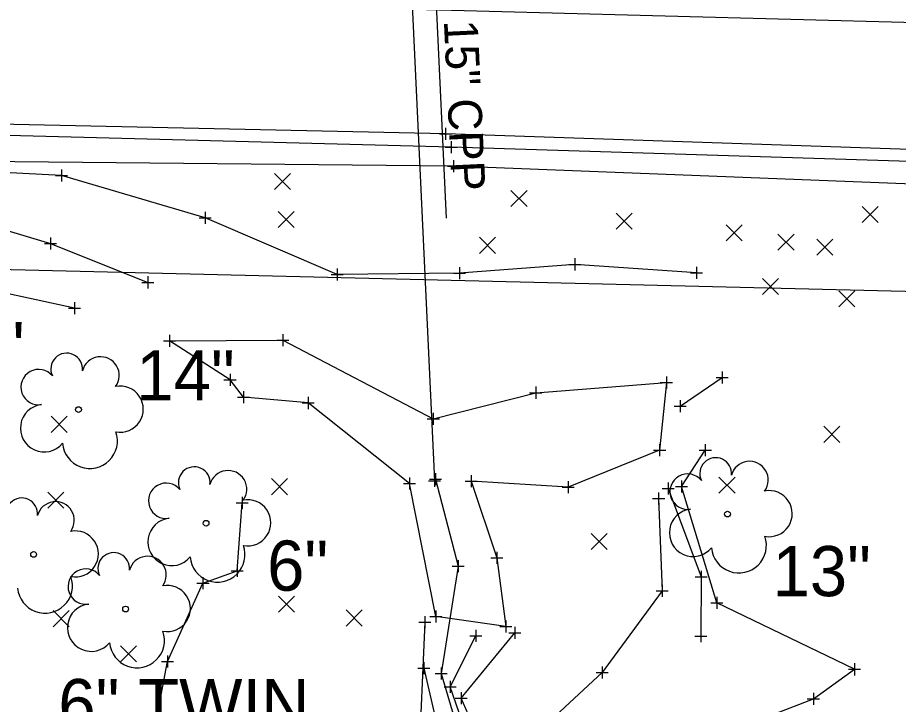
# Model space of a CAD drawing. Extents: x 2005176 to 2005823, y 572472 to 572942.
# Drawn here: x 2005491.4 to 2005564.6, y 572551.1 to 572608.1 of the extents above; entities that cross this region are included whole.
import ezdxf

# ---------------------------------------------------------------- set-up
doc = ezdxf.new("R2010")
doc.units = 0
for name, color, linetype in [('_CIVIL_CONSTRUCTION', 7, 'Continuous'), ('DR_X_Storm_Sewer', 7, 'Continuous'), ('DR_X_Text', 7, 'Continuous'), ('GE_X_Alignment_100_Bearings', 7, 'Continuous'), ('GE_X_Alignment_100_Cardinal_Points', 7, 'Continuous'), ('GE_X_Alignment_100_Distances', 7, 'Continuous'), ('GE_X_Alignment_100_Stations', 7, 'Continuous'), ('GE_X_Alignment_500_Bearings', 7, 'Continuous'), ('GE_X_Alignment_500_Cardinal_Points', 7, 'Continuous'), ('GE_X_Alignment_500_Curve_Data', 7, 'Continuous'), ('GE_X_Alignment_500_Distances', 7, 'Continuous'), ('SC_Scratch10', 7, 'Continuous'), ('SC_Scratch8', 7, 'Continuous'), ('SV_P_Mon_Cells_Set', 7, 'Continuous'), ('SV_X_Random_Point', 7, 'Continuous'), ('SV_X_Shot_Marker', 7, 'Continuous'), ('UT_X_Overhead_Telecom', 7, 'Continuous'), ('VG_X_Text', 7, 'Continuous')]:
    doc.layers.add(name, color=color, linetype=linetype)

msp = doc.modelspace()

# ---------------------------------------------------------------- linework, layer by layer
at = {"layer": '_CIVIL_CONSTRUCTION'}
for p, q in [((2005525.539, 572569.63), (2005526.539, 572569.63)), ((2005526.039, 572570.13), (2005526.039, 572569.13)), ((2005526.039, 572569.63), (2005526.039, 572569.63))]:
    msp.add_line(p, q, dxfattribs=at)
at = {"layer": 'DR_X_Storm_Sewer'}
msp.add_line((2005522.925, 572635.917), (2005526.039, 572569.63), dxfattribs=at)
at = {"layer": 'DR_X_Text'}
msp.add_line((2005527.042, 572591.446), (2005526.156, 572610.296), dxfattribs=at)
at = {"layer": 'GE_X_Alignment_100_Bearings'}
msp.add_lwpolyline([(2005818.636, 572588.972), (2005775.196, 572590.402), (2005728.29, 572591.88), (2005676.677, 572593.613), (2005626.55, 572595.194), (2005577.828, 572596.717), (2005526.97, 572598.442), (2005477.007, 572599.528), (2005423.668, 572600.697), (2005368.746, 572601.993), (2005321.745, 572602.994), (2005266.716, 572604.351), (2005220.033, 572605.659)], dxfattribs=at)
at = {"layer": 'GE_X_Alignment_100_Cardinal_Points'}
msp.add_lwpolyline([(2005220.502, 572615.986), (2005272.509, 572614.367), (2005322.2, 572613.202), (2005370.615, 572612.292), (2005424.944, 572611.274), (2005476.504, 572610.167), (2005524.324, 572608.789), (2005576.491, 572607.397), (2005627.688, 572605.768), (2005677.107, 572603.684), (2005728.026, 572601.917), (2005776.184, 572600.497), (2005820.14, 572599.28)], dxfattribs=at)
at = {"layer": 'GE_X_Alignment_100_Distances'}
msp.add_lwpolyline([(2005818.697, 572589.047), (2005775.196, 572590.402), (2005728.29, 572591.88), (2005676.677, 572593.613), (2005626.55, 572595.194), (2005577.828, 572596.717), (2005526.97, 572598.442), (2005477.007, 572599.528), (2005423.668, 572600.697), (2005368.746, 572601.993), (2005321.745, 572602.994), (2005266.716, 572604.351), (2005220.057, 572605.648)], dxfattribs=at)
at = {"layer": 'GE_X_Alignment_100_Stations'}
for points in [[(2005470.12, 572593.875), (2005474.272, 572594.058), (2005485.559, 572591.913), (2005494.153, 572589.341), (2005502.252, 572586.105)], [(2005526.126, 572569.752), (2005528.014, 572562.539), (2005526.605, 572553.625), (2005531.765, 572536.046), (2005521.073, 572519.95), (2005516.881, 572512.197), (2005511.963, 572508.178), (2005509.477, 572499.914), (2005500.59, 572492.24)]]:
    msp.add_lwpolyline(points, dxfattribs=at)
at = {"layer": 'GE_X_Alignment_500_Bearings'}
for points in [[(2005547.792, 572586.884), (2005537.69, 572587.6), (2005528.11, 572586.874), (2005517.957, 572586.766), (2005507.009, 572591.458), (2005495.082, 572594.973), (2005470.451, 572596.25)], [(2005496.157, 572583.959), (2005486.828, 572585.976), (2005475.498, 572587.61), (2005465.973, 572587.901)], [(2005546.432, 572575.82), (2005549.93, 572578.201)], [(2005539.868, 572544.991), (2005550.848, 572548.934), (2005557.502, 572551.51), (2005560.928, 572553.964), (2005549.485, 572559.497), (2005546.556, 572569.14), (2005548.532, 572572.172)], [(2005545.436, 572568.995), (2005548.18, 572561.658), (2005548.151, 572556.721)], [(2005544.658, 572568.151), (2005544.953, 572560.493), (2005539.957, 572553.713), (2005533.75, 572547.927), (2005532.487, 572545.893)], [(2005500.74, 572496.501), (2005502.666, 572505.833), (2005503.248, 572514.147), (2005499.084, 572526.483), (2005502.215, 572545.864), (2005503.875, 572554.617), (2005506.82, 572561.115), (2005509.657, 572562.142), (2005510.083, 572567.796)], [(2005510.836, 572502.456), (2005513.462, 572507.883), (2005515.078, 572510.249), (2005522.31, 572520.302), (2005528.373, 572530.257), (2005532.552, 572533.09), (2005530.012, 572544.855), (2005527.353, 572552.501), (2005529.477, 572556.747)], [(2005525.157, 572554.054), (2005527.24, 572545.068), (2005530.901, 572535.974), (2005520.467, 572520.575), (2005515.869, 572512.981), (2005511.264, 572509.493), (2005507.53, 572498.68)]]:
    msp.add_lwpolyline(points, dxfattribs=at)
at = {"layer": 'GE_X_Alignment_500_Cardinal_Points'}
for points in [[(2005525.242, 572557.882), (2005524.719, 572545.929), (2005528.063, 572537.211), (2005518.106, 572522.096), (2005515.293, 572513.45), (2005509.953, 572509.45), (2005507.414, 572501.497)], [(2005505.489, 572493.647), (2005512.611, 572502.332), (2005515.602, 572509.525), (2005522.377, 572518.182), (2005528.142, 572526.059), (2005534.669, 572529.98), (2005534.351, 572537.981), (2005532.172, 572545.253), (2005530.581, 572546.261), (2005528.258, 572551.573), (2005532.711, 572557)]]:
    msp.add_lwpolyline(points, dxfattribs=at)
at = {"layer": 'GE_X_Alignment_500_Curve_Data'}
msp.add_lwpolyline([(2005531.976, 572557.522), (2005526.16, 572558.356), (2005523.973, 572569.398), (2005515.559, 572576.086), (2005510.176, 572576.581), (2005509.063, 572578.011), (2005504.042, 572581.252), (2005513.441, 572581.309), (2005525.946, 572574.778), (2005534.445, 572576.941), (2005545.295, 572577.775), (2005544.74, 572572.177), (2005537.136, 572569.084), (2005529.092, 572569.6), (2005531.217, 572563.214)], close=True, dxfattribs=at)
at = {"layer": 'GE_X_Alignment_500_Distances'}
msp.add_lwpolyline([(2005220.405, 572616.044), (2005272.509, 572614.367), (2005322.2, 572613.202), (2005370.615, 572612.292), (2005424.944, 572611.274), (2005476.504, 572610.167), (2005524.324, 572608.789), (2005576.491, 572607.397), (2005627.688, 572605.768), (2005677.107, 572603.684), (2005728.026, 572601.917), (2005776.184, 572600.497), (2005820.136, 572599.258)], dxfattribs=at)
at = {"layer": 'SC_Scratch10'}
msp.add_lwpolyline([(2005818.546, 572585.941), (2005774.935, 572587.721), (2005728.191, 572589.228), (2005676.714, 572591.115), (2005626.893, 572592.621), (2005577.772, 572593.782), (2005527.621, 572595.745), (2005477.172, 572596.247), (2005467.62, 572596.601)], dxfattribs=at)
at = {"layer": 'SC_Scratch8'}
msp.add_lwpolyline([(2005818.664, 572586.636), (2005775.011, 572588.281), (2005728.162, 572589.789), (2005676.746, 572591.584), (2005626.726, 572593.575), (2005577.921, 572595.757), (2005527.418, 572597.322), (2005476.909, 572598.652), (2005423.434, 572599.267), (2005368.772, 572600.603), (2005321.591, 572601.671), (2005267.034, 572602.727), (2005220.031, 572603.934)], dxfattribs=at)
at = {"layer": 'SV_P_Mon_Cells_Set'}
for p, q in [((2005526.97, 572598.942), (2005526.97, 572597.942)), ((2005526.97, 572598.942), (2005526.97, 572597.942)), ((2005526.47, 572598.442), (2005527.47, 572598.442)), ((2005526.47, 572598.442), (2005527.47, 572598.442)), ((2005526.97, 572598.442), (2005526.97, 572598.442)), ((2005526.97, 572598.442), (2005526.97, 572598.442)), ((2005526.918, 572597.322), (2005527.918, 572597.322)), ((2005527.418, 572597.822), (2005527.418, 572596.822)), ((2005527.418, 572597.322), (2005527.418, 572597.322)), ((2005527.621, 572596.245), (2005527.621, 572595.245)), ((2005495.082, 572595.473), (2005495.082, 572594.473)), ((2005527.121, 572595.745), (2005528.121, 572595.745)), ((2005527.621, 572595.745), (2005527.621, 572595.745)), ((2005494.582, 572594.973), (2005495.582, 572594.973)), ((2005495.082, 572594.973), (2005495.082, 572594.973)), ((2005506.509, 572591.458), (2005507.509, 572591.458)), ((2005507.009, 572591.958), (2005507.009, 572590.958)), ((2005507.009, 572591.458), (2005507.009, 572591.458)), ((2005493.653, 572589.341), (2005494.653, 572589.341)), ((2005494.153, 572589.841), (2005494.153, 572588.841)), ((2005494.153, 572589.341), (2005494.153, 572589.341)), ((2005537.69, 572588.1), (2005537.69, 572587.1)), ((2005517.957, 572587.266), (2005517.957, 572586.266)), ((2005528.11, 572587.374), (2005528.11, 572586.374)), ((2005537.19, 572587.6), (2005538.19, 572587.6)), ((2005537.69, 572587.6), (2005537.69, 572587.6)), ((2005547.792, 572587.384), (2005547.792, 572586.384)), ((2005502.252, 572586.605), (2005502.252, 572585.605)), ((2005517.457, 572586.766), (2005518.457, 572586.766)), ((2005517.957, 572586.766), (2005517.957, 572586.766)), ((2005527.61, 572586.874), (2005528.61, 572586.874)), ((2005528.11, 572586.874), (2005528.11, 572586.874)), ((2005547.292, 572586.884), (2005548.292, 572586.884)), ((2005547.792, 572586.884), (2005547.792, 572586.884)), ((2005501.752, 572586.105), (2005502.752, 572586.105)), ((2005502.252, 572586.105), (2005502.252, 572586.105)), ((2005496.157, 572584.459), (2005496.157, 572583.459)), ((2005495.657, 572583.959), (2005496.657, 572583.959)), ((2005496.157, 572583.959), (2005496.157, 572583.959)), ((2005503.542, 572581.252), (2005504.542, 572581.252)), ((2005504.042, 572581.752), (2005504.042, 572580.752)), ((2005504.042, 572581.252), (2005504.042, 572581.252)), ((2005512.941, 572581.309), (2005513.941, 572581.309)), ((2005513.441, 572581.809), (2005513.441, 572580.809)), ((2005513.441, 572581.309), (2005513.441, 572581.309)), ((2005509.063, 572578.511), (2005509.063, 572577.511)), ((2005545.295, 572578.275), (2005545.295, 572577.275)), ((2005549.93, 572578.701), (2005549.93, 572577.701)), ((2005508.563, 572578.011), (2005509.563, 572578.011)), ((2005509.063, 572578.011), (2005509.063, 572578.011)), ((2005544.795, 572577.775), (2005545.795, 572577.775)), ((2005545.295, 572577.775), (2005545.295, 572577.775)), ((2005549.43, 572578.201), (2005550.43, 572578.201)), ((2005549.93, 572578.201), (2005549.93, 572578.201)), ((2005510.176, 572577.081), (2005510.176, 572576.081)), ((2005533.945, 572576.941), (2005534.945, 572576.941)), ((2005534.445, 572577.441), (2005534.445, 572576.441)), ((2005534.445, 572576.941), (2005534.445, 572576.941)), ((2005509.676, 572576.581), (2005510.676, 572576.581)), ((2005510.176, 572576.581), (2005510.176, 572576.581)), ((2005515.059, 572576.086), (2005516.059, 572576.086)), ((2005515.559, 572576.586), (2005515.559, 572575.586)), ((2005515.559, 572576.086), (2005515.559, 572576.086)), ((2005546.432, 572576.32), (2005546.432, 572575.32)), ((2005545.932, 572575.82), (2005546.932, 572575.82)), ((2005546.432, 572575.82), (2005546.432, 572575.82)), ((2005525.446, 572574.778), (2005526.446, 572574.778)), ((2005525.946, 572575.278), (2005525.946, 572574.278)), ((2005525.946, 572574.778), (2005525.946, 572574.778)), ((2005544.74, 572572.677), (2005544.74, 572571.677)), ((2005548.532, 572572.672), (2005548.532, 572571.672)), ((2005544.24, 572572.177), (2005545.24, 572572.177)), ((2005544.74, 572572.177), (2005544.74, 572572.177)), ((2005548.032, 572572.172), (2005549.032, 572572.172)), ((2005548.532, 572572.172), (2005548.532, 572572.172)), ((2005526.126, 572570.252), (2005526.126, 572569.252)), ((2005523.973, 572569.898), (2005523.973, 572568.898)), ((2005525.626, 572569.752), (2005526.626, 572569.752)), ((2005526.126, 572569.752), (2005526.126, 572569.752)), ((2005528.592, 572569.6), (2005529.592, 572569.6)), ((2005529.092, 572570.1), (2005529.092, 572569.1)), ((2005529.092, 572569.6), (2005529.092, 572569.6)), ((2005537.136, 572569.584), (2005537.136, 572568.584)), ((2005545.436, 572569.495), (2005545.436, 572568.495)), ((2005546.556, 572569.64), (2005546.556, 572568.64)), ((2005523.473, 572569.398), (2005524.473, 572569.398)), ((2005523.973, 572569.398), (2005523.973, 572569.398)), ((2005536.636, 572569.084), (2005537.636, 572569.084)), ((2005537.136, 572569.084), (2005537.136, 572569.084)), ((2005544.936, 572568.995), (2005545.936, 572568.995)), ((2005545.436, 572568.995), (2005545.436, 572568.995)), ((2005546.056, 572569.14), (2005547.056, 572569.14)), ((2005546.556, 572569.14), (2005546.556, 572569.14)), ((2005510.083, 572568.296), (2005510.083, 572567.296)), ((2005544.158, 572568.151), (2005545.158, 572568.151)), ((2005544.658, 572568.651), (2005544.658, 572567.651)), ((2005544.658, 572568.151), (2005544.658, 572568.151)), ((2005509.583, 572567.796), (2005510.583, 572567.796)), ((2005510.083, 572567.796), (2005510.083, 572567.796)), ((2005531.217, 572563.714), (2005531.217, 572562.714)), ((2005528.014, 572563.039), (2005528.014, 572562.039)), ((2005530.717, 572563.214), (2005531.717, 572563.214)), ((2005531.217, 572563.214), (2005531.217, 572563.214)), ((2005509.157, 572562.142), (2005510.157, 572562.142)), ((2005509.657, 572562.642), (2005509.657, 572561.642)), ((2005509.657, 572562.142), (2005509.657, 572562.142)), ((2005527.514, 572562.539), (2005528.514, 572562.539)), ((2005528.014, 572562.539), (2005528.014, 572562.539)), ((2005548.18, 572562.158), (2005548.18, 572561.158)), ((2005506.82, 572561.615), (2005506.82, 572560.615)), ((2005547.68, 572561.658), (2005548.68, 572561.658)), ((2005548.18, 572561.658), (2005548.18, 572561.658)), ((2005506.32, 572561.115), (2005507.32, 572561.115)), ((2005506.82, 572561.115), (2005506.82, 572561.115)), ((2005544.953, 572560.993), (2005544.953, 572559.993)), ((2005544.453, 572560.493), (2005545.453, 572560.493)), ((2005544.953, 572560.493), (2005544.953, 572560.493)), ((2005549.485, 572559.997), (2005549.485, 572558.997)), ((2005548.985, 572559.497), (2005549.985, 572559.497)), ((2005549.485, 572559.497), (2005549.485, 572559.497)), ((2005526.16, 572558.856), (2005526.16, 572557.856)), ((2005524.742, 572557.882), (2005525.742, 572557.882)), ((2005525.242, 572558.382), (2005525.242, 572557.382)), ((2005525.242, 572557.882), (2005525.242, 572557.882)), ((2005525.66, 572558.356), (2005526.66, 572558.356)), ((2005526.16, 572558.356), (2005526.16, 572558.356)), ((2005531.976, 572558.022), (2005531.976, 572557.022)), ((2005529.477, 572557.247), (2005529.477, 572556.247)), ((2005531.476, 572557.522), (2005532.476, 572557.522)), ((2005531.976, 572557.522), (2005531.976, 572557.522)), ((2005532.711, 572557.5), (2005532.711, 572556.5)), ((2005548.151, 572557.221), (2005548.151, 572556.221)), ((2005528.977, 572556.747), (2005529.977, 572556.747)), ((2005529.477, 572556.747), (2005529.477, 572556.747)), ((2005532.211, 572557), (2005533.211, 572557)), ((2005532.711, 572557), (2005532.711, 572557)), ((2005547.651, 572556.721), (2005548.651, 572556.721)), ((2005548.151, 572556.721), (2005548.151, 572556.721)), ((2005503.875, 572555.117), (2005503.875, 572554.117)), ((2005503.375, 572554.617), (2005504.375, 572554.617)), ((2005503.875, 572554.617), (2005503.875, 572554.617)), ((2005525.157, 572554.554), (2005525.157, 572553.554)), ((2005526.605, 572554.125), (2005526.605, 572553.125)), ((2005539.957, 572554.213), (2005539.957, 572553.213)), ((2005560.928, 572554.464), (2005560.928, 572553.464)), ((2005524.657, 572554.054), (2005525.657, 572554.054)), ((2005525.157, 572554.054), (2005525.157, 572554.054)), ((2005526.105, 572553.625), (2005527.105, 572553.625)), ((2005526.605, 572553.625), (2005526.605, 572553.625)), ((2005539.457, 572553.713), (2005540.457, 572553.713)), ((2005539.957, 572553.713), (2005539.957, 572553.713)), ((2005560.428, 572553.964), (2005561.428, 572553.964)), ((2005560.928, 572553.964), (2005560.928, 572553.964)), ((2005527.353, 572553.001), (2005527.353, 572552.001)), ((2005526.853, 572552.501), (2005527.853, 572552.501)), ((2005527.353, 572552.501), (2005527.353, 572552.501)), ((2005528.258, 572552.073), (2005528.258, 572551.073)), ((2005557.502, 572552.01), (2005557.502, 572551.01)), ((2005527.758, 572551.573), (2005528.758, 572551.573)), ((2005528.258, 572551.573), (2005528.258, 572551.573)), ((2005557.002, 572551.51), (2005558.002, 572551.51)), ((2005557.502, 572551.51), (2005557.502, 572551.51))]:
    msp.add_line(p, q, dxfattribs=at)
at = {"layer": 'SV_X_Random_Point'}
for p, q in [((2005512.766, 572593.814), (2005514.099, 572595.149)), ((2005512.766, 572595.149), (2005514.099, 572593.814)), ((2005532.395, 572592.408), (2005533.729, 572593.743)), ((2005532.395, 572593.743), (2005533.729, 572592.408)), ((2005561.56, 572591.081), (2005562.893, 572592.416)), ((2005561.56, 572592.416), (2005562.893, 572591.081)), ((2005513.063, 572590.648), (2005514.396, 572591.983)), ((2005513.063, 572591.983), (2005514.396, 572590.648)), ((2005541.134, 572590.51), (2005542.467, 572591.845)), ((2005541.134, 572591.845), (2005542.467, 572590.51)), ((2005550.263, 572589.549), (2005551.596, 572590.884)), ((2005550.263, 572590.884), (2005551.596, 572589.549)), ((2005554.567, 572588.782), (2005555.9, 572590.117)), ((2005554.567, 572590.117), (2005555.9, 572588.782)), ((2005529.79, 572588.515), (2005531.123, 572589.85)), ((2005529.79, 572589.85), (2005531.123, 572588.515)), ((2005557.781, 572588.362), (2005559.114, 572589.697)), ((2005557.781, 572589.697), (2005559.114, 572588.362)), ((2005553.271, 572585.102), (2005554.605, 572586.437)), ((2005553.271, 572586.437), (2005554.605, 572585.102)), ((2005559.605, 572584.068), (2005560.938, 572585.402)), ((2005559.605, 572585.402), (2005560.938, 572584.068)), ((2005494.201, 572573.646), (2005495.534, 572574.981)), ((2005494.201, 572574.981), (2005495.534, 572573.646)), ((2005558.363, 572572.817), (2005559.697, 572574.152)), ((2005558.363, 572574.152), (2005559.697, 572572.817)), ((2005512.506, 572568.469), (2005513.839, 572569.804)), ((2005512.506, 572569.804), (2005513.839, 572568.469)), ((2005549.664, 572568.593), (2005550.997, 572569.928)), ((2005549.664, 572569.928), (2005550.997, 572568.593)), ((2005493.927, 572567.34), (2005495.26, 572568.674)), ((2005493.927, 572568.674), (2005495.26, 572567.34)), ((2005539.041, 572563.922), (2005540.374, 572565.257)), ((2005539.041, 572565.257), (2005540.374, 572563.922)), ((2005513.088, 572558.71), (2005514.421, 572560.045)), ((2005513.088, 572560.045), (2005514.421, 572558.71)), ((2005494.382, 572557.507), (2005495.715, 572558.842)), ((2005494.382, 572558.842), (2005495.715, 572557.507)), ((2005518.71, 572557.557), (2005520.043, 572558.892)), ((2005518.71, 572558.892), (2005520.043, 572557.557)), ((2005499.958, 572554.583), (2005501.291, 572555.919)), ((2005499.958, 572555.919), (2005501.291, 572554.583))]:
    msp.add_line(p, q, dxfattribs=at)
at = {"layer": 'SV_X_Shot_Marker'}
for centre in [(2005496.486, 572575.539), (2005550.375, 572566.858), (2005507.075, 572566.096), (2005492.756, 572563.511), (2005500.395, 572558.974)]:
    msp.add_circle(centre, 0.24, dxfattribs=at)
for centre, radius, start, end in [((2005495.502, 572578.907), 1.317, 354.0047, 205.97412), ((2005498.312, 572578.368), 1.553, 323.82996, 165.0376), ((2005493.177, 572577.403), 1.471, 39.06254, 279.54124), ((2005499.946, 572575.575), 1.915, 259.14531, 101.45961), ((2005493.633, 572573.991), 1.974, 96.17219, 320.57371), ((2005497.433, 572572.934), 2.284, 184.94757, 19.45715), ((2005549.392, 572570.226), 1.317, 354.0047, 205.97412), ((2005552.202, 572569.687), 1.553, 323.82996, 165.0376), ((2005506.092, 572569.464), 1.317, 354.0047, 205.97412), ((2005508.902, 572568.925), 1.553, 323.82996, 165.0376), ((2005547.066, 572568.722), 1.471, 39.06254, 279.54124), ((2005503.766, 572567.96), 1.471, 39.06254, 279.54124), ((2005553.836, 572566.894), 1.915, 259.14531, 101.45961), ((2005491.772, 572566.878), 1.317, 354.0047, 205.97412), ((2005510.536, 572566.132), 1.915, 259.14531, 101.45961), ((2005494.582, 572566.34), 1.553, 323.82996, 165.0376), ((2005547.522, 572565.31), 1.974, 96.17219, 320.57371), ((2005504.222, 572564.548), 1.974, 96.17219, 320.57371), ((2005496.216, 572563.547), 1.915, 259.14531, 101.45961), ((2005551.322, 572564.253), 2.284, 184.94757, 19.45715), ((2005499.411, 572562.342), 1.317, 354.0047, 205.97412), ((2005508.022, 572563.491), 2.284, 184.94757, 19.45715), ((2005502.221, 572561.803), 1.553, 323.82996, 165.0376), ((2005497.085, 572560.838), 1.471, 39.06254, 279.54124), ((2005493.702, 572560.906), 2.284, 184.94757, 19.45715), ((2005503.855, 572559.01), 1.915, 259.14531, 101.45961), ((2005497.541, 572557.426), 1.974, 96.17219, 320.57371), ((2005501.341, 572556.369), 2.284, 184.94757, 19.45715)]:
    msp.add_arc(centre, radius, start, end, dxfattribs=at)
at = {"layer": 'UT_X_Overhead_Telecom'}
msp.add_line((2005468.843, 572587.718), (2005612.939, 572584.192), dxfattribs=at)

# ---------------------------------------------------------------- texts
at = {"layer": 'DR_X_Text'}
msp.add_text('15" CPP', height=2.8, rotation=272.68979, dxfattribs=at).set_placement((2005526.819, 572607.847))
at = {"layer": 'VG_X_Text'}
for s, p in [('18"', (2005483.819, 572578.637)), ('14"', (2005501.283, 572576.305)), ('6"', (2005512.146, 572560.495)), ('13"', (2005554.11, 572560.039)), ('6" TWIN', (2005494.808, 572548.992))]:
    msp.add_text(s, height=4.1667, dxfattribs=at).set_placement(p)

doc.saveas('drawing.dxf')
